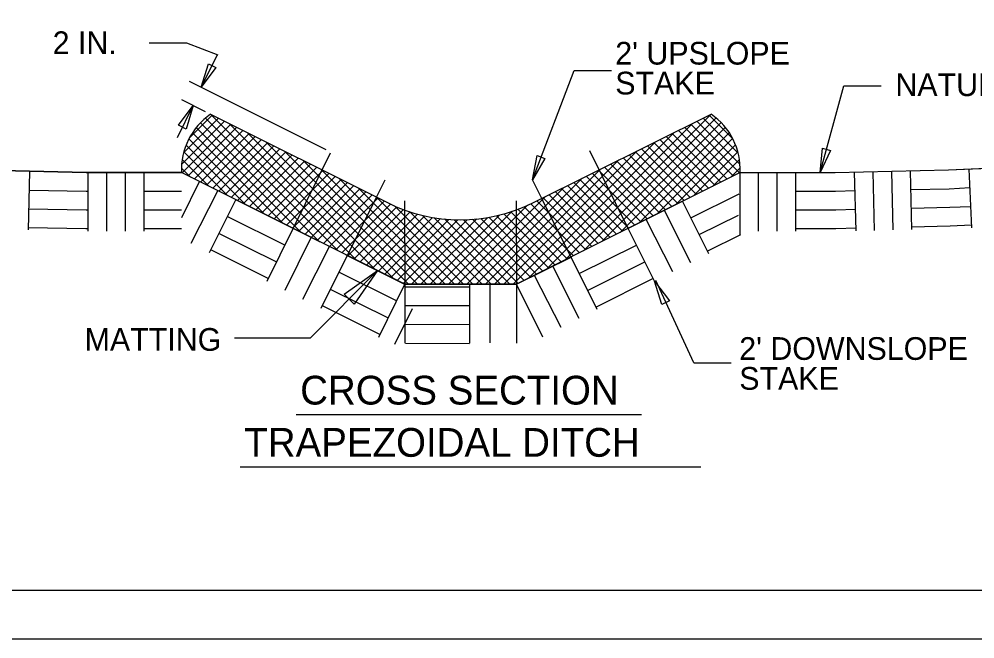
# Model space of a CAD drawing. Extents: x 8096 to 9796, y 9620 to 10720.
# Drawn here: x 8436.8 to 8876.7, y 9619.8 to 9905.1 of the extents above; entities that cross this region are included whole.
import ezdxf

# ---------------------------------------------------------------- set-up
doc = ezdxf.new("R2010")
doc.units = 0
for name, color, linetype in [('Blank Plan Sheet Both CELL', 7, 'Continuous'), ('Default', 7, 'Continuous'), ('Old_Level_1', 7, 'Continuous'), ('Old_Level_2', 7, 'Continuous'), ('Old_Level_20', 7, 'Continuous'), ('Sheet Plot Border Outside CELL', 7, 'Continuous')]:
    doc.layers.add(name, color=color, linetype=linetype)

msp = doc.modelspace()

# ---------------------------------------------------------------- linework, layer by layer
at = {"layer": 'Blank Plan Sheet Both CELL'}
msp.add_lwpolyline([(9762.02, 10692.33), (8262.02, 10692.33), (8262.02, 9642.33), (9762.02, 9642.33)], close=True, dxfattribs=at)
at = {"layer": 'Default'}
for p, q in [((8512.48, 9843.56), (8528.5, 9859.57)), ((8515.2, 9850.51), (8525.67, 9860.98)), ((8522.54, 9859.49), (8583.6, 9798.43)), ((8524.93, 9861.34), (8592.09, 9794.18)), ((8524.94, 9861.35), (8606.31, 9820.66)), ((8673.26, 9820.59), (8755.32, 9861.42)), ((8688.01, 9794.22), (8755.09, 9861.31)), ((8696.5, 9798.47), (8757.66, 9859.63)), ((8751.58, 9859.56), (8767.74, 9843.4)), ((8754.41, 9860.97), (8765.16, 9850.22)), ((8511.61, 9838.44), (8531.32, 9858.15)), ((8511.79, 9834.38), (8534.15, 9856.74)), ((8514.62, 9832.96), (8536.98, 9855.33)), ((8518.33, 9855.22), (8566.61, 9806.94)), ((8520.34, 9857.46), (8575.1, 9802.69)), ((8533.41, 9857.11), (8600.59, 9789.93)), ((8679.53, 9789.98), (8746.65, 9857.11)), ((8704.98, 9802.71), (8759.85, 9857.58)), ((8713.47, 9806.95), (8761.84, 9855.33)), ((8743.08, 9855.33), (8765.46, 9832.95)), ((8745.91, 9856.74), (8768.29, 9834.36)), ((8748.75, 9858.15), (8768.56, 9838.34)), ((8514.97, 9850.09), (8549.62, 9815.44)), ((8516.54, 9852.77), (8558.12, 9811.19)), ((8517.45, 9831.55), (8539.81, 9853.91)), ((8520.27, 9830.13), (8542.64, 9852.5)), ((8523.1, 9828.72), (8545.47, 9851.08)), ((8541.89, 9852.87), (8609.08, 9785.68)), ((8671.04, 9785.74), (8738.21, 9852.9)), ((8721.95, 9811.19), (8763.62, 9852.86)), ((8730.44, 9815.44), (8765.18, 9850.18)), ((8734.58, 9851.1), (8756.98, 9828.71)), ((8737.41, 9852.51), (8759.8, 9830.12)), ((8740.25, 9853.92), (8762.63, 9831.53)), ((8513.65, 9847.17), (8541.13, 9819.7)), ((8525.93, 9827.3), (8548.29, 9849.67)), ((8528.76, 9825.89), (8551.12, 9848.26)), ((8531.58, 9824.47), (8553.95, 9846.84)), ((8550.38, 9848.63), (8615.94, 9783.07)), ((8664.13, 9783.07), (8729.76, 9848.7)), ((8723.25, 9845.46), (8745.66, 9823.05)), ((8726.08, 9846.87), (8748.49, 9824.46)), ((8728.91, 9848.28), (8751.32, 9825.88)), ((8731.75, 9849.69), (8754.15, 9827.29)), ((8738.92, 9819.68), (8766.51, 9847.27)), ((8512.6, 9843.98), (8532.63, 9823.95)), ((8534.41, 9823.06), (8556.78, 9845.43)), ((8537.24, 9821.64), (8559.61, 9844.01)), ((8540.07, 9820.23), (8562.44, 9842.6)), ((8542.89, 9818.81), (8565.27, 9841.18)), ((8558.86, 9844.39), (8620.18, 9783.07)), ((8659.88, 9783.07), (8721.32, 9844.5)), ((8714.75, 9841.23), (8737.18, 9818.81)), ((8717.58, 9842.64), (8740, 9820.22)), ((8720.42, 9844.05), (8742.83, 9821.64)), ((8747.41, 9823.92), (8767.58, 9844.09)), ((8511.85, 9840.49), (8524.14, 9828.2)), ((8545.72, 9817.4), (8568.09, 9839.77)), ((8548.55, 9815.98), (8570.92, 9838.36)), ((8551.37, 9814.57), (8573.75, 9836.94)), ((8567.35, 9840.14), (8624.42, 9783.07)), ((8655.64, 9783.07), (8712.88, 9840.3)), ((8706.25, 9837.01), (8728.69, 9814.56)), ((8709.08, 9838.42), (8731.52, 9815.98)), ((8711.92, 9839.82), (8734.35, 9817.39)), ((8755.89, 9828.16), (8768.29, 9840.57)), ((8764.38, 9832.41), (8768.62, 9836.65)), ((8511.5, 9836.59), (8515.64, 9832.45)), ((8554.2, 9813.15), (8576.58, 9835.53)), ((8557.03, 9811.74), (8579.41, 9834.11)), ((8559.86, 9810.32), (8582.24, 9832.7)), ((8575.83, 9835.9), (8628.67, 9783.07)), ((8651.4, 9783.07), (8704.43, 9836.1)), ((8697.75, 9832.78), (8720.21, 9810.32)), ((8700.58, 9834.19), (8723.03, 9811.74)), ((8703.42, 9835.6), (8725.86, 9813.15)), ((8562.68, 9808.9), (8585.06, 9831.28)), ((8565.51, 9807.49), (8587.89, 9829.87)), ((8568.34, 9806.07), (8590.72, 9828.46)), ((8584.32, 9831.66), (8632.91, 9783.07)), ((8647.16, 9783.07), (8695.99, 9831.9)), ((8689.25, 9828.55), (8711.72, 9806.08)), ((8692.08, 9829.96), (8714.55, 9807.49)), ((8694.92, 9831.37), (8717.38, 9808.91)), ((8571.17, 9804.66), (8593.55, 9827.04)), ((8573.99, 9803.24), (8596.38, 9825.63)), ((8576.82, 9801.83), (8599.21, 9824.21)), ((8592.8, 9827.41), (8637.15, 9783.07)), ((8638.67, 9783.07), (8679.1, 9823.5)), ((8642.91, 9783.07), (8687.55, 9827.7)), ((8680.75, 9824.32), (8703.24, 9801.84)), ((8683.58, 9825.73), (8706.06, 9803.25)), ((8686.42, 9827.14), (8708.89, 9804.66)), ((8579.65, 9800.41), (8602.03, 9822.8)), ((8582.48, 9799), (8604.86, 9821.39)), ((8585.3, 9797.58), (8607.72, 9820)), ((8601.29, 9823.17), (8641.39, 9783.07)), ((8609.55, 9819.16), (8645.64, 9783.07)), ((8634.43, 9783.07), (8670.82, 9819.46)), ((8672.24, 9820.1), (8694.75, 9797.59)), ((8675.09, 9821.5), (8697.58, 9799.01)), ((8677.92, 9822.91), (8700.41, 9800.42)), ((8588.13, 9796.17), (8610.64, 9818.68)), ((8590.96, 9794.75), (8613.68, 9817.47)), ((8593.79, 9793.34), (8616.84, 9816.39)), ((8596.61, 9791.92), (8620.11, 9815.42)), ((8616.42, 9816.53), (8649.88, 9783.07)), ((8622.38, 9814.81), (8654.12, 9783.07)), ((8625.94, 9783.07), (8657.84, 9814.96)), ((8630.19, 9783.07), (8663.79, 9816.67)), ((8659.9, 9815.47), (8683.44, 9791.94)), ((8663.14, 9816.47), (8686.26, 9793.35)), ((8666.28, 9817.58), (8689.09, 9794.77)), ((8669.31, 9818.8), (8691.92, 9796.18)), ((8599.44, 9790.51), (8623.51, 9814.57)), ((8602.27, 9789.09), (8627.04, 9813.86)), ((8605.09, 9787.68), (8630.72, 9813.3)), ((8607.92, 9786.26), (8634.59, 9812.93)), ((8610.75, 9784.84), (8638.67, 9812.76)), ((8613.58, 9783.43), (8642.96, 9812.81)), ((8617.46, 9783.07), (8647.53, 9813.14)), ((8621.7, 9783.07), (8652.46, 9813.83)), ((8627.67, 9813.76), (8658.36, 9783.07)), ((8632.55, 9813.13), (8662.61, 9783.07)), ((8637.09, 9812.82), (8666.47, 9783.45)), ((8641.37, 9812.79), (8669.29, 9784.87)), ((8645.42, 9812.98), (8672.12, 9786.28)), ((8649.28, 9813.37), (8674.95, 9787.69)), ((8652.96, 9813.92), (8677.78, 9789.11)), ((8656.5, 9814.63), (8680.61, 9790.52)), ((8665.7, 9783.07), (8691.22, 9795.77))]:
    msp.add_line(p, q, dxfattribs=at)
for points in [[(8768.62, 9834.53), (8665.7, 9783.07), (8614.3, 9783.07), (8511.5, 9834.53)], [(8742.19, 9821.33), (8665.7, 9783.07), (8614.3, 9783.07), (8536.56, 9821.98)], [(8587.18, 9796.64), (8614.48, 9782.98), (8665.7, 9783.07)]]:
    msp.add_lwpolyline(points, dxfattribs=at)
for centre, radius, start, end in [((8542.4, 9835.81), 30.93, 124.3737, 182.3852), ((8737.81, 9836.03), 30.84, 357.2093, 55.4088), ((8639.85, 9887.74), 75, 243.4349, 296.4513)]:
    msp.add_arc(centre, radius, start, end, dxfattribs=at)
at = {"layer": 'Old_Level_1'}
for p, q in [((8496.68, 9894.18), (8513.82, 9894.18)), ((8513.82, 9894.18), (8528.24, 9888.69)), ((8520.79, 9874.05), (8528.07, 9888.76)), ((8673.01, 9831.23), (8692.28, 9881.54)), ((8692.28, 9881.54), (8709.41, 9881.54)), ((8805.44, 9834.53), (8816.42, 9874.37)), ((8816.42, 9874.37), (8833.49, 9874.37)), ((8511.5, 9868.07), (8522.38, 9862.66)), ((8509.66, 9850.66), (8516.94, 9865.36)), ((8562.9, 9808.8), (8580.14, 9843.61)), ((8717.16, 9808.8), (8699.4, 9844.49)), ((8864.57, 9835.69), (8916.78, 9838.07)), ((8441.05, 9808.1), (8441.74, 9834.99)), ((8468.63, 9807.46), (8468.63, 9834.53)), ((8477.17, 9807.46), (8477.17, 9834.53)), ((8485.77, 9807.46), (8485.77, 9834.53)), ((8494.36, 9807.46), (8494.36, 9834.53)), ((8768.62, 9805.78), (8768.62, 9834.53)), ((8768.62, 9834.53), (8812.35, 9834.53)), ((8777.16, 9807.46), (8777.16, 9834.53)), ((8785.75, 9807.46), (8785.75, 9834.53)), ((8794.29, 9807.46), (8794.29, 9834.53)), ((8812.35, 9834.53), (8864.57, 9835.69)), ((8821.99, 9807.69), (8821.35, 9834.7)), ((8830.53, 9807.81), (8829.95, 9834.88)), ((8839.13, 9808.1), (8838.43, 9834.99)), ((8847.72, 9808.22), (8847.03, 9835.28)), ((8875.31, 9809.09), (8874.09, 9836.1)), ((8511.61, 9813.85), (8519.8, 9830.35)), ((8601.24, 9823.2), (8605.2, 9831.2)), ((8677.35, 9822.5), (8673.01, 9831.23)), ((8516.03, 9801.94), (8528.2, 9826.17)), ((8524.45, 9797.76), (8536.58, 9821.97)), ((8575.86, 9772.06), (8601.24, 9823.2)), ((8614.12, 9821.43), (8614.29, 9783.07)), ((8665.59, 9821.43), (8665.75, 9783.09)), ((8702.81, 9771.44), (8677.35, 9822.5)), ((8754.21, 9797.12), (8742.19, 9821.34)), ((8745.97, 9792.94), (8733.89, 9817.1)), ((8737.66, 9788.76), (8725.46, 9812.92)), ((8550.88, 9784.52), (8562.9, 9808.8)), ((8729.24, 9784.52), (8717.16, 9808.8)), ((8559.18, 9780.34), (8571.2, 9804.62)), ((8567.43, 9776.21), (8579.62, 9800.49)), ((8694.51, 9767.27), (8682.43, 9791.37)), ((8686.2, 9763.15), (8674, 9787.19)), ((8747.39, 9746.94), (8729.79, 9784.78)), ((8602.28, 9758.79), (8614.3, 9783.07)), ((8614.29, 9783.07), (8614.29, 9756.01)), ((8644.04, 9783.07), (8644.04, 9756)), ((8653.39, 9783.07), (8653.39, 9756.18)), ((8677.78, 9758.79), (8665.7, 9783.07)), ((8665.75, 9783.09), (8665.75, 9756.03)), ((8609.77, 9755.48), (8617.9, 9771.92)), ((8747.39, 9746.94), (8764.53, 9746.94))]:
    msp.add_line(p, q, dxfattribs=at)
for points in [[(8514.99, 9876.56), (8578.01, 9845.19)], [(8511.5, 9834.53), (8467.7, 9834.53), (8415.43, 9835.69), (8363.22, 9838.07)], [(8363.22, 9838.07), (8415.43, 9835.69), (8467.7, 9834.53), (8511.5, 9834.53)], [(8768.62, 9834.53), (8812.35, 9834.53), (8864.57, 9835.69), (8916.78, 9838.07)], [(8441.57, 9826.4), (8467.59, 9825.93), (8468.63, 9825.93)], [(8494.36, 9825.93), (8511.5, 9825.93)], [(8745.97, 9813.73), (8768.15, 9824.65)], [(8794.29, 9825.93), (8812.53, 9825.93), (8821.59, 9826.22)], [(8847.14, 9826.69), (8864.86, 9827.09), (8874.44, 9827.56)], [(8441.28, 9817.86), (8467.59, 9817.34), (8468.63, 9817.34)], [(8494.36, 9817.34), (8511.5, 9817.34)], [(8749.86, 9805.95), (8767.92, 9814.9)], [(8794.29, 9817.34), (8812.64, 9817.34), (8821.82, 9817.63)], [(8847.43, 9818.15), (8865.15, 9818.56), (8874.73, 9818.96)], [(8532.75, 9814.32), (8559.18, 9801.13)], [(8847.55, 9809.55), (8865.38, 9809.96), (8875.14, 9810.37)], [(8441.16, 9809.26), (8467.41, 9808.8), (8468.63, 9808.8)], [(8494.36, 9808.8), (8511.5, 9808.8)], [(8528.92, 9806.47), (8555.23, 9793.41)], [(8753.52, 9798.34), (8768.97, 9805.95)], [(8794.29, 9808.8), (8812.76, 9808.8), (8822.11, 9809.09)], [(8525.15, 9798.87), (8551.51, 9785.74)], [(8694.51, 9788), (8720.93, 9801.13)], [(8698.4, 9780.28), (8724.77, 9793.41)], [(8584.16, 9788.59), (8610.58, 9775.4)], [(8702.17, 9772.61), (8728.54, 9785.74)], [(8580.26, 9780.74), (8606.69, 9767.68)], [(8644.21, 9781.73), (8614.71, 9781.73)], [(8576.6, 9773.19), (8602.92, 9760.01)], [(8644.04, 9773.19), (8614.59, 9773.19)], [(8644.04, 9764.48), (8614.59, 9764.6)], [(8644.04, 9755.6), (8614.59, 9755.77)]]:
    msp.add_lwpolyline(points, dxfattribs=at)
at = {"layer": 'Old_Level_2'}
for points in [[(8520.64, 9873.75), (8523.88, 9884.6), (8527.36, 9882.85)], [(8516.94, 9865.36), (8513.67, 9854.52), (8510.19, 9856.28)], [(8805.44, 9834.53), (8806.49, 9845.74), (8810.26, 9844.69)], [(8673.01, 9831.23), (8675.21, 9842.32), (8678.81, 9840.93)], [(8601.74, 9789.35), (8590.94, 9773.9), (8586.35, 9778.55)], [(8729.24, 9784.52), (8736.1, 9775.52), (8732.67, 9773.75)]]:
    msp.add_lwpolyline(points, close=True, dxfattribs=at)
msp.add_lwpolyline([(8601.74, 9789.35), (8570.79, 9758.34), (8535.94, 9758.34)], dxfattribs=at)
at = {"layer": 'Old_Level_20'}
for p, q in [((8564.29, 9723.13), (8723.31, 9723.13)), ((8538.45, 9699.08), (8750.61, 9699.08))]:
    msp.add_line(p, q, dxfattribs=at)
at = {"layer": 'Sheet Plot Border Outside CELL'}
msp.add_lwpolyline([(8095.52, 9619.83), (9795.52, 9619.83), (9795.52, 10719.83), (8095.52, 10719.83)], close=True, dxfattribs=at)

# ---------------------------------------------------------------- texts
at = {"layer": 'Old_Level_1'}
for s, height, p in [('2 IN.', 10.454, (8452.21, 9889.04)), ("2' UPSLOPE", 10.454, (8711.17, 9884.22)), ('STAKE', 10.454, (8711.17, 9870.46)), ('NATURAL GROUND', 10.4544, (8840.11, 9869.72)), ("2' DOWNSLOPE", 10.4544, (8768.24, 9748.28)), ('STAKE', 10.454, (8768.24, 9734.52)), ('CROSS SECTION', 13.2422, (8566.15, 9727.72)), ('TRAPEZOIDAL DITCH', 13.2422, (8540.42, 9703.67))]:
    msp.add_text(s, height=height, dxfattribs=at).set_placement(p)
at = {"layer": 'Old_Level_2'}
msp.add_text('MATTING', height=10.454, dxfattribs=at).set_placement((8466.93, 9752.46))

doc.saveas('drawing.dxf')
